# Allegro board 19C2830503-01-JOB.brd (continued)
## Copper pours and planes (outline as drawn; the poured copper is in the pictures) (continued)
N13254578 on TOP: 116.26,127.89 117.35,127.89 118.24,128.78 118.82,128.78 118.97,128.63 118.97,128.24 118.26,127.53 116.26,127.53 116.15,127.63 116.15,127.79
N13268176 on TOP: 82.02,138.81 82.02,150.47 82.09,150.55 82.45,150.55 82.55,150.44 82.55,143.74 84.07,142.21 87.66,142.21 88.04,141.83 88.04,138.71 87.63,138.3 82.52,138.3
N13268280 on TOP: 81.23,150.39 81.38,150.55 81.64,150.55 81.76,150.42 81.76,138.71 81.31,138.25 76.89,138.25 76.43,138.71 76.43,142.04 76.68,142.29 80.24,142.29 81.23,143.28
N14335696 on TOP: 13.36,99.11 20.57,99.11 21.84,100.38 21.84,103.59 22.28,104.03 24.79,104.03 25.31,103.5 25.31,99.17 24.71,98.58 13.36,98.58 13.26,98.68 13.26,99.01
N14335800 on TOP: 13.41,98.3 24.61,98.3 25.3,97.61 25.3,93.22 24.97,92.89 22.07,92.89 21.82,93.14 21.82,97.36 21.44,97.74 13.39,97.74 13.26,97.87 13.26,98.15
N14337048 on TOP: 24.21,88.27 24.69,87.78 24.69,85.34 24.61,85.27 24.46,85.27 24.38,85.34 24.38,87.13 23.7,87.82 23.05,87.82 22.1,88.77 22.1,90.42 22.35,90.68 24,90.68 24.21,90.47
N14344366 on TOP: 21.23,88.19 21.69,88.19 22.38,87.5 23.55,87.5 24.23,86.82 24.23,85.39 24.13,85.29 23.95,85.29 23.88,85.37 23.88,86.46 23.34,87 21.59,87 21.08,87.5 21.08,88.04
N14711749 on TOP: 127.13,132.79 127.13,130.43 127.25,130.3 128.02,130.3 128.39,130.68 128.39,134.33 128.23,134.49 126.59,134.49 126.31,134.21 126.31,133.6
N14994125 on TOP: 128.27,66.88 128.63,66.52 128.63,62.36 128.19,61.93 125.78,61.93 125.5,62.2 125.5,66.68 125.7,66.88
N16784180 on BOTTOM: 52.65,124.26 59.18,124.26 59.36,124.08 59.36,123.49 59.16,123.29 52.68,123.29 52.5,123.47 52.5,124.1
N16825817 on TOP: 109.37,173.43 110.08,173.43 110.19,173.53 110.19,174.62 110.52,174.96 110.52,175.34 110.34,175.51 109.52,175.51 109.27,175.26 109.27,173.53
N16825817 on BOTTOM: 112.9,175.77 112.9,173.23 112.65,172.97 110.9,172.97 109.88,173.99 106.81,173.99 106.55,174.24 106.55,175.67 106.83,175.95 112.73,175.95
N16827286 on TOP: 111.63,160.53 111.25,160.91 111.25,165.61 109.73,167.13 109.73,169.42 109.98,169.67 111.12,169.67 111.38,169.42 111.38,168.53 115.06,164.85 115.06,160.78 114.81,160.53
N17000861 on TOP: 120.52,172.97 120.78,172.72 120.78,171.83 121.28,171.32 123.7,171.32 124.84,172.47 124.84,174.62 124.59,174.88 119.51,174.88 119.25,174.62 119.25,173.23 119.51,172.97
N17000861 on BOTTOM: 123.38,175.96 123.7,175.64 123.7,173.23 123.44,172.97 121.79,172.97 121.54,173.23 121.54,175.64 121.86,175.96
N17761475 on TOP: 20.7,49.15 21.21,49.66 21.21,50.67 21.08,50.8 19.94,50.8 19.81,50.67 19.81,48.13 19.18,47.5 14.61,47.5 14.35,47.24 14.35,46.61 14.29,46.55 13.3,46.55 12.85,46.99 12.85,48.21 12.73,48.34 9.6,48.34 9.53,48.26 9.53,46.61 10.59,45.54 10.59,45.34 11.18,44.75 12.17,44.75 13.36,43.56 19.3,43.56 20.7,44.96
N17761475 on BOTTOM: 19.68,43.18 19.94,43.43 19.94,46.74 19.18,47.5 15.11,47.5 14.86,47.75 14.86,48.89 14.61,49.15 13.59,49.15 13.21,48.77 13.21,43.56 13.59,43.18
N18495858 on TOP: 136.7,79.91 133.2,79.91 133.02,79.73 132.16,79.73 132.08,79.65 132.08,76.89 132.21,76.76 132.89,76.76 133.12,76.99 133.12,78.46 133.32,78.66 136.37,78.66 136.75,79.04 136.75,79.86
N18495926 on TOP: 131.83,72.9 130.94,72.9 130.81,72.77 130.81,68.71 130.94,68.58 131.7,68.58 131.95,68.83 131.95,72.77
N18823007 on BOTTOM: 130.17,33.1 129.36,33.1 128.9,33.56 128.04,33.56 127.79,33.31 127.79,31.85 127.98,31.66 130.08,31.66 130.26,31.84 130.26,33
N18823875 on BOTTOM: 57.06,148.91 54.68,148.91 54.58,148.81 54.58,148.09 54.69,147.98 55.38,147.98 56.21,147.15 56.82,147.15 57.14,147.47 57.14,148.83
N44510100 on TOP: 130,167.49 130.61,167.49 130.68,167.41 130.68,166.62 130.7,166.61 130.7,165.9 131.19,165.4 133.6,165.4 134.06,164.95 134.06,159.08 133.48,158.5 129.51,158.5 129.01,159 129.01,164.16 129.87,165.02 129.87,167.36
N44510146 on TOP: 130.67,171.92 130.2,171.45 130.2,169.95 130.15,169.9 129.46,169.9 129.39,169.98 129.39,174.6 129.54,174.75 132.59,174.75 132.84,174.5 132.84,172.97 132.59,172.72 130.94,172.72 130.67,172.45
N44510146 on BOTTOM: 129.67,174.24 133.73,174.24 133.86,174.12 133.86,172.34 133.6,172.09 129.54,172.09 129.41,172.21 129.41,173.99
N66015725 on TOP: 172.47,40.39 174.5,40.39 176.02,38.86 178.18,38.86 178.82,39.5 178.82,41.91 178.31,42.42 175.9,42.42 175.26,41.78 173.74,41.78 172.47,43.05 170.31,43.05 170.18,42.93 170.18,41.66 170.31,41.53 171.32,41.53

Small or netless copper shapes (teardrops, artwork), in the pictures only: 147 on TOP, 8 on L8

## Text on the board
Ref Des/Silkscreen Bottom: A1 | J | E | Y | C | W | H | A | X | Z | DSPM-8305E AMC REV:A104-1 | MADE IN | 19C2830503-01
Ref Des/Silkscreen Top: AH | AW | Y | K | B | C | L | AH1 | AA | E | N | AD | U | AQ | DD | zz | AC | AU | J | EE | V | AR | M | AK | AL | AT | AS | D | AM | AV | vv | AN | CC | AP | P | A | W | MM | X | K2EVM-HK | ENET1 | ENET0
BODY_CENTER: 69.25 | 85.10 | 140.75 | 146.80 | 144.20 | 4.25 | 112.08 | 87.08 | 8.00 | R | 0.50 | 180.60 | 1.00 | 172.10 | 173.90 | 169.80 | 168.10 | dia | 171.60 | 2.35 | 54.61 | (*4) | 147.95 | 27.31 | 6.00 | 0.66 | 25.91 | (*2) | 135.31 | 24.39 | 48.77 | 81.18 | 126.72 | 1.70 | 3.50 | 146.15 | 7.00 | 5.30 | 41.71 | 30.40 | 26.81 | 137.77 | 95.28 | 26.10 | 12.00 | 1.50 | 20.60 | 22.60 | 9.00 | 15.01 | 11.48 | 13.60 | 14.36 | 9.86 | 6.85 | 3.85 | 3.75 | 0.85 | 0 | 107.20 | 88.52 | 2.70 | 135.35 | 129.00 | 123.00 | 117.00 | 111.00 | 97.20 | 1.60 | 148.50 | 147.50 | 145.35 | 143.30 | 43.15 | 21.32 | 11.50 | 4.80 | 3.25 | 1.10
DISPLAY_BOTTOM: 8.00 | 1.70 | 13.54 | 0 | 12.00 | 144.60 | 4.55
DIMENSION: 8.00 | 1.70 | 13.54 | 6.85 | 0 | 12.00 | 144.60 | 4.55
User.5: 69.25 | 85.10 | 140.75 | 146.80 | 144.20 | 4.25 | 112.08 | 87.08 | 8.00 | R | 0.50 | 180.60 | 1.00 | 172.10 | 173.90 | 169.80 | 168.10 | dia | 171.60 | 2.35 | 54.61 | (*4) | 147.95 | 27.31 | 6.00 | 0.66 | 25.91 | (*2) | 135.31 | 24.39 | 48.77 | 81.18 | 126.72 | 1.70 | 3.50 | 146.15 | 7.00 | 41.71 | 26.81 | 137.77 | 95.28 | 26.10 | 12.00 | 1.50 | 20.60 | 22.60 | 9.00 | 15.01 | 11.48 | 13.60 | 14.36 | 9.86 | 6.85 | 3.85 | 3.75 | 0.85 | 0 | 107.20 | 88.52 | 2.70 | 135.35 | 129.00 | 123.00 | 117.00 | 111.00 | 97.20 | 1.60 | 148.50 | 147.50 | 145.35 | 143.30 | 43.15 | 21.32 | 11.50 | 4.80 | 3.25 | 1.10
User.6: J31 | J30 | B | A
User.7: BOTTOM SIDE H=2.0mm
User.11: FIGURE | SIZE | 10.0 | 12.0 | 14.0 | 18.0 | 28.0 | 32.0 | 35.0 | 38.0 | 40.0 | 41.0 | 45.0 | 60.0 | 63.0 | 70.0 | 91.0 | 93.0 | 106.0 | 125.0 | 138.0 | 156.0 | 26.0 | 37.0 | 42.0 | 43.0 | 128.0 | 32.0x22.0 | 75.0x38.0 | 118.0x32.0 | 138.0x40.0 | 421.0x67.0 | DRILL CHART: TOP to BOTTOM | ALL UNITS ARE IN MILS | TOLERANCE | +0.0/-0.0 | PLATED | NON-PLATED | QTY | 3691 | 219 | 1208 | 320 | 9 | 6 | 20 | 16 | 8 | 1 | 2 | 4 | 3 | 17 | 5591 | TOTAL HOLES:
User.12: FIGURE | SIZE | 18.0 | 20.0 | DRILL CHART: L5 to BOTTOM | ALL UNITS ARE IN MILS | TOLERANCE | +0.0/-0.0 | PLATED | NON-PLATED | QTY | 2 | 4 | 6 | TOTAL HOLES:
